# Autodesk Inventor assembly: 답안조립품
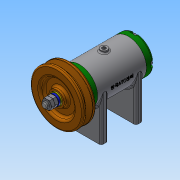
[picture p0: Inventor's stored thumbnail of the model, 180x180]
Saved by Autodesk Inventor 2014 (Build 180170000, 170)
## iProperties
Created: 2020-07
Part Number: 답안조립품
Document SubType Name: Assembly
Designer: net
Author: net
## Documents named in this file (15)
- C:\Users\net\Desktop\700706V1031\답안조립품.iam
- C:\Users\net\Desktop\700706V1031\V벨트풀리.ipt
- C:\Users\net\Desktop\700706V1031\답안본체.ipt
- C:\Users\net\Desktop\700706V1031\축.ipt
- C:\Users\net\Desktop\700706V1031\키 3x3x12.ipt
- C:\Users\net\Desktop\700706V1031\스프링와셔 8.ipt
- C:\Users\net\Desktop\700706V1031\와셔 8x17.ipt
- C:\Users\net\Desktop\700706V1031\너트 M8.ipt
- C:\Users\net\Desktop\700706V1031\베어링 6002.ipt
- C:\Users\net\Desktop\700706V1031\볼트 M4x12.ipt
- C:\Users\net\Desktop\700706V1031\앞커버.ipt
- C:\Users\net\Desktop\700706V1031\오일 실 15 25 7.ipt
- C:\Users\net\Desktop\700706V1031\뒤커버.ipt
- C:\Users\net\Desktop\700706V1031\볼트 M6x8.ipt
- C:\Users\net\Desktop\700706V1031\와셔 6x11.5.ipt
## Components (1 placed, 1 different names)
1. V벨트풀리:1
